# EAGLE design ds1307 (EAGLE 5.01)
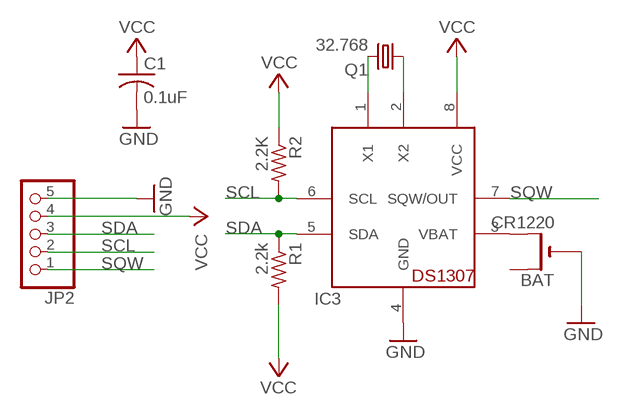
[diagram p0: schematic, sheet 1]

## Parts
BAT  CR1220  CR1220THM  [CR1220-THM]
C1  0.1uF  C-US025-025X050  [C025-025X050]
IC3  DS1307  [DIL08]
JP2  PINHD-1X5  [1X05]
Q1  32.768  CRYTALTC38H  [TC38H]
R1  2.2k  R-US_0207/10  [0207/10]
R2  2.2K  R-US_0207/10  [0207/10]

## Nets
GND: BAT.- C1.2 IC3.4(GND) JP2.5
N$14: IC3.1(X1) Q1.2
N$15: IC3.2(X2) Q1.1
N$39: BAT.+2(+1) IC3.3(VBAT)
SCL: IC3.6(SCL) JP2.2 R2.2
SDA: IC3.5(SDA) JP2.3 R1.1
SQW: IC3.7(SQW/OUT) JP2.1
VCC: C1.1 IC3.8(VCC) JP2.4 R1.2 R2.1
Unconnected: BAT.+1(+)

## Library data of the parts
BAT = adafruit:CR1220: CR1216/CR1220/CR1225 12mm 3V lithium coin cell Great for battery packup. Both SMT and THM holders. Note the THM package has the ground pads on both sides of the PCB so that the masks are the same - this reduces the cost
C1 = adafruit:C-US: CAPACITOR, American symbol
IC3 = adafruit:DS1307: DS1307 Real time clock (RTC) with battery backup ability. Talk to it via i2c
JP2 = pinhead:PINHD-1X5: PIN HEADER
Q1 = crystal:CRYTAL: CRYSTAL
R1 R2 = adafruit:R-US_: RESISTOR, American symbol

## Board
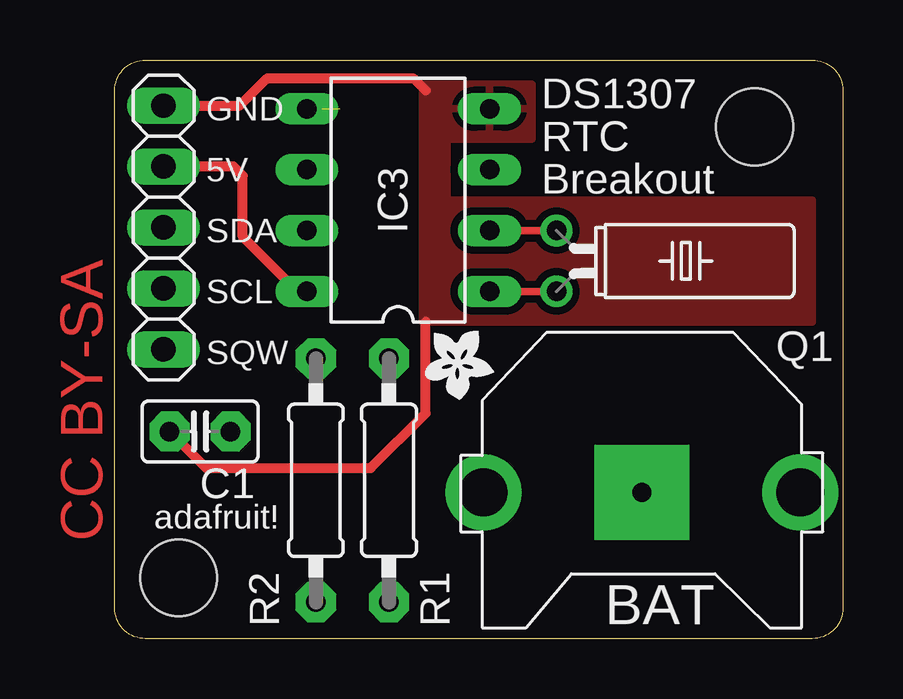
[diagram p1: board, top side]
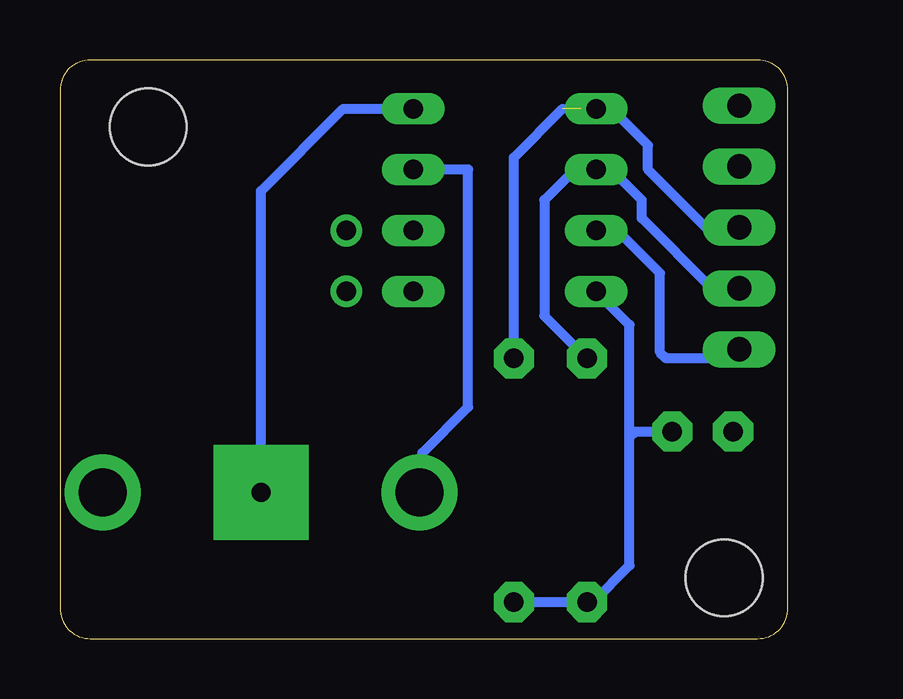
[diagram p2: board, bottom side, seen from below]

Size 30.35 x 24.13 mm. Coordinates in mm from the lower left corner, seen from the top.
Outline: 0,22.86 arc-90 1.27,24.13 29.08,24.13 arc-90 30.35,22.86 30.35,1.27 arc-90 29.08,0 1.27,0 arc-90 0,1.27 0,22.86
Copper layers (1*16): Top 0.035mm / dielectric 1.5mm / Bottom 0.035mm
Design rules "default *": minimum track width 10mil, minimum drill 20mil, track to track 12mil, track to pad 12mil, pad to pad 10mil, via to via 12mil, smd to smd 0mil, copper to edge 20mil, drill to drill 8mil, minimum pad ring 10mil, minimum via ring 8mil, stop-mask expansion 4mil, vias tented up to drill 20mil, thermal gap 10mil
Holes 3.2 mm at 26.67,21.34 2.67,2.54

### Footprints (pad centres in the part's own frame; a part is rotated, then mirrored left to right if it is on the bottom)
CR1220-THM = drill 2 pad 3.175 round: +1 -6.604,0; +2 6.604,0 | drill 0.8 pad 3.962 square: - 0,0
C025-025X050 = drill 0.813 pad 1.676 octagon: 1 -1.27,0; 2 1.27,0
DIL08 = drill 0.813 long: 1 -3.81,-3.81; 2 -1.27,-3.81; 3 1.27,-3.81; 4 3.81,-3.81; 5 3.81,3.81; 6 1.27,3.81; 7 -1.27,3.81; 8 -3.81,3.81
1X05 = drill 1.016 long: 1 -5.08,0; 2 -2.54,0; 3 0,0; 4 2.54,0; 5 5.08,0
TC38H = drill 0.813 round: 1 -1.27,0; 2 1.27,0
0207/10 = drill 0.813 pad 1.676 octagon: 1 -5.08,0; 2 5.08,0

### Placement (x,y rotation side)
BAT  21.97,6.1 180 top
C1  3.56,8.64 180 top
IC3  11.81,18.29 90 top
JP2  2.03,17.14 90 top
Q1  18.41,15.75 270 top
R1  11.43,6.6 270 top
R2  8.38,6.6 90 top
U$1  [ADAFRUIT200MIL]  14.48,11.43 180 top

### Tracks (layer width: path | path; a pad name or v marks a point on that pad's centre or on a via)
GND
  Top 0.406: IC3.4 15.49,22.1 | JP2.5 5.21,22.23 6.35,23.37 12.45,23.37 12.95,22.86 | C1.2 3.81,7.11 10.67,7.11 12.95,9.4 12.95,13.21
  Bottom 0.406: BAT.- 21.97,18.67 18.54,22.1 IC3.4
  pour Top: 12.83,23.11 12.83,13.21 29.08,13.21 29.08,18.29 13.84,18.29 13.84,20.83 17.4,20.83 17.4,23.11
N$14
  Top 0.305: IC3.1 15.88,14.48 arc-90 16,14.35 arc-90 16.13,14.48 Q1.2
N$15
  Top 0.305: IC3.2 Q1.1
N$39
  Bottom 0.406: IC3.3 13.34,19.56 13.34,9.65 15.24,7.75 15.24,6.1 BAT.+2
SCL
  Bottom 0.406: R2.2 10.16,13.46 10.16,18.29 8.89,19.56 IC3.6 | IC3.6 7.87,19.56 | JP2.2 3.17,14.61 6.1,17.53 6.1,18.29 7.11,19.3 7.62,19.3 8,19.68 | 8,19.68 8.13,19.81 | 8,19.68 IC3.6
SDA  (1 unrouted)
  Bottom 0.406: R1.1 11.43,20.07 9.4,22.1 | JP2.3 3.43,17.14 5.84,19.56 5.84,20.57 7.37,22.1 IC3.5 8.64,22.1
SQW
  Bottom 0.406: IC3.7 7.11,17.02 5.33,15.24 5.33,11.94 5.08,11.68 2.54,11.68 2.29,11.94 1.91,11.94 | 1.78,11.94 1.91,11.94 | 1.91,11.94 JP2.1
VCC
  Top 0.406: JP2.4 4.95,19.68 5.33,19.3 5.33,16.76 7.62,14.48 IC3.8
  Bottom 0.406: IC3.8 6.6,13.08 6.6,8.38 | 6.6,8.38 6.6,3.05 8.13,1.52 R2.1 R1.2 | C1.1 6.35,8.64 6.6,8.38

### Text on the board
Top: CC BY-SA
tPlace: GND | DS1307 | RTC | 5V | Breakout | SDA | SCL | SQW | adafruit!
